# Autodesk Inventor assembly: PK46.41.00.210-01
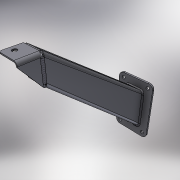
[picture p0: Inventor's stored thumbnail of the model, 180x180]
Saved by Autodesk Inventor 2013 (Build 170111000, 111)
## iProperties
Created: 2012-02
Part Number: PK46.41.00.210-01
Document SubType Name: Weldment
Designer: tedescj
Weld Material: Welded Aluminum-6061
Author: tedescj
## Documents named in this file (5)
- C:\Vault Workspace\Front Loader\Data\Assy, Chassis, Front\PK46.41.00.210-01.iam
- C:\Vault Workspace\Front Loader\Data\Assy, Chassis, Front\PK46.41.00.011.ipt
- C:\Vault Workspace\Front Loader\Data\Assy, Chassis, Front\PK46.41.00.012-01.ipt
- C:\Vault Workspace\Front Loader\Data\Assy, Chassis, Front\PK46.41.00.011-01.ipt
- C:\Vault Workspace\Front Loader\Data\Assy, Chassis, Front\PK46.41.00.013.ipt
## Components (4 placed, 4 different names)
1. PK46.41.00.011:1
2. PK46.41.00.012-01:1
3. PK46.41.00.011-01:1
4. PK46.41.00.013:1
